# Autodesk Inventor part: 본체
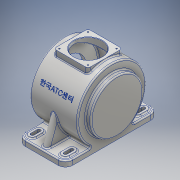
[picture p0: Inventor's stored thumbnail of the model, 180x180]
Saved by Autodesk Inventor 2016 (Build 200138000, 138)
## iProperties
Created: 2015-06
Part Number: 본체
Material: 알루미늄 6061
Document SubType Name: Modeling
Designer: Administrator
Density: 2.7 g/cm^3
Appearance: 알루미늄 - 평지
Mass: 3263.51 g
Surface Area: 2302.96 cm^2
Volume: 1208.71 cm^3
Author: Administrator
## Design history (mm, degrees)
sketch "스케치1"
  geometry: C1 r 85 at (0, 0); 1 further point
  constraints: 1 centre point, 1 coincident
  dimensions: "d0" = 170 diameter of C1
extrude "돌출1" new body sketch "스케치1" stored distance "d1" = 118; taper "d3" = 0 deg; dims "d2" = 51, "d4" = 0
sketch "스케치3"
  geometry: C1 r 65 at (0, 0); 1 further point
  constraints: 1 centre point, 1 coincident
  dimensions: "d5" = 130 diameter of C1
extrude "돌출2" join sketch "스케치3" distance "d6" = 13; taper "d7" = 0 deg
sketch "스케치4"
  geometry: C1 r 65 at (0, 0); 1 further point
  constraints: 1 centre point, 1 coincident
  dimensions: "d8" = 130 diameter of C1
extrude "돌출3" join sketch "스케치4" distance "d9" = 3; taper "d10" = 0 deg
sketch "스케치7"
  geometry: L1 (71, -115)-(85, -115); L2 (85, -115)-(85, 115); L3 (85, 115)-(71, 115); L4 (71, 115)-(71, -115); 2 further points
  constraints: 8 end point, 2 parallel, 1 horizontal, 1 horizontal alignment, 1 midpoint, 1 perpendicular
  dimensions: "d16" = 14 distance of L2.end L3.end; "d17" = 230 distance of L3.end L1.start; "d18" = 85 distance from line of L2 point (0, 0)
extrude "돌출5" join sketch "스케치7" stored distance "d19" = 3; taper "d20" = 0 deg
sketch "스케치8"
  geometry: L1 (-62, 65)-(-62, -65) reference; L2 (-59, -85)-(59, -85) reference; L3 (-59, 85)-(59, 85) reference; L4 (72, 0)-(-62, 0); L5 (-51, 47.5)-(-51, 77); L6 (-51, 77)-(51, 77); L7 (51, 77)-(51, 31); L8 (51, 31)-(47.5, 29.368); L9 (47.5, 29.368)-(47.5, 23.5); L10 (47.5, 23.5)-(61.5, 23.5); L11 (61.5, 23.5)-(61.5, 15); L12 (61.5, 15)-(64.5, 15); L13 (72, -65)-(72, 65) reference; L14 (64.5, 15)-(64.5, 0); L15 (-51, 47.5)-(-62, 47.5); L16 (-62, 47.5)-(-62, 0); 1 further point
  constraints: 24 end point, 5 perpendicular, 2 midpoint, 2 point on line, 1 parallel, 1 vertical
  dimensions: "d21" = 3 distance of L11.end L12.end; "d23" = 30 diameter of L12 L4; "d24" = 14 distance of L9.end L10.end; "d25" = 47 diameter of L10 L4; "d26" = 115 deg angle of L7 L8; "d27" = 102 distance between parallel lines of L5 L7; "d28" = 62 diameter of L7.end L4; "d29" = 154 diameter of L6 L4; "d30" = 95 diameter of L15 L4; "d31" = 11 distance of L5.start L15.end; "d32" = 3.5 distance from line of L7 L8.end
revolve "회전1" sketch "스케치8" stored, may be unused: angle "d33" = 90 deg
sketch "스케치9"
  geometry: L1 (-115, -71)-(-46.733, -71) reference; L2 (115, -85)-(-115, -85) reference; L3 (46.733, -71)-(115, -71) reference; L4 (-42.5, 88)-(42.5, 88); L5 (42.5, 88)-(42.5, 73.612); L6 (-42.5, 73.612)-(-42.5, 88); A1 r 85 centre (0, 0) between (46.733, -71) and (-46.733, -71) reference; 1 further point
  constraints: 6 end point, 2 parallel, 2 point on circle, 1 horizontal, 1 perpendicular
  dimensions: "d34" = 85 distance of L4.start L4.end; "d35" = 173 distance between parallel lines of L2 L4
extrude "돌출6" join sketch "스케치9" stored distance "d36" = 85; taper "d37" = 0 deg
sketch "스케치10"
  geometry: 2 further points
  constraints: 1 coincident
hole "구멍1" sketch "스케치10" at (42.5, 42.5) diameter "d38" = 70; stored, may be unused: countersink angle "d42" = 90 deg, drill point angle "d44" = 118 deg; dims "d39" = 6, "d40" = 4, "d41" = 2, "d43" = 8
fillet "모깎기1" dims "d45" = 7
sketch "스케치11"
  geometry: L1 (0, 78)-(71, 78); L2 (71, 78)-(71, 7); L3 (71, 7)-(0, 7); L4 (0, 7)-(0, 78); 7 further points
  constraints: 8 end point, 4 coincident, 2 midpoint, 2 parallel, 2 perpendicular, 1 horizontal, 1 horizontal alignment, 1 vertical alignment
  dimensions: "d46" = 71 distance of L1.start L1.end
hole "구멍2" sketch "스케치11" at (0, 78), (0, 7), (71, 7), (71, 78) diameter "d47" = 3.242; stored, may be unused: countersink angle "d51" = 90 deg, drill point angle "d53" = 118 deg; dims "d48" = 10, "d49" = 4, "d50" = 2, "d52" = 13
sketch "스케치12"
  geometry: A1 r 55 centre (0, 0) between (0, 55) and (55, 0); 3 further points
  constraints: 4 point on circle, 2 horizontal alignment, 2 vertical alignment, 1 centre point, 1 coincident
  dimensions: "d54" = 110 diameter of A1
hole "구멍3" sketch "스케치12" at (0, 55), (55, 0), (0, -55), (-55, 0) diameter "d55" = 3.242; stored, may be unused: countersink angle "d59" = 90 deg, drill point angle "d61" = 118 deg; dims "d56" = 8, "d57" = 4, "d58" = 2, "d60" = 11.8
sketch "스케치14"
  geometry: L1 (-115, -71)-(-46.733, -71) reference; L2 (-109, -71)-(-84.87, -4.703); L3 (-109, -71)-(-46.733, -71); A1 r 85 centre (0, 0) between (46.733, -71) and (-46.733, -71) reference; 1 further point
  constraints: 4 end point, 1 horizontal, 1 point on circle, 1 point on line
  dimensions: "d62" = 6 distance of L1.start L2.start; "d63" = 110 deg angle of L1 L2
extrude "돌출7" join sketch "스케치14" stored distance "d64" = 15; taper "d65" = 0 deg
sketch "스케치16"
  geometry: L1 (-18, 25.267)-(-18, 25.267); L2 (-9, 34.267)-(-9, 50.267); L3 (-18, 59.267)-(-18, 59.267); L4 (-27, 50.267)-(-27, 34.267); L5 (0, 68.267)-(-118, 68.267) reference; L6 (0, -161.733)-(0, 68.267) reference; L7 (0, -46.733)-(-118, -46.733); L8 (-118, 68.267)-(-118, -161.733) reference; L9 (-27, -127.733)-(-27, -143.733); L10 (-9, -143.733)-(-9, -127.733); L11 (-109, 50.267)-(-109, 34.267); L12 (-91, 34.267)-(-91, 50.267); L13 (-109, -127.733)-(-109, -143.733); L14 (-91, -143.733)-(-91, -127.733); A1 r 9 centre (-18, 50.267) between (-18, 59.267) and (-27, 50.267); A2 r 9 centre (-18, 50.267) between (-9, 50.267) and (-18, 59.267); A3 r 9 centre (-18, 34.267) between (-27, 34.267) and (-18, 25.267); A4 r 9 centre (-18, 34.267) between (-18, 25.267) and (-9, 34.267); A5 r 9 centre (-18, -143.733) between (-27, -143.733) and (-18, -152.733); A6 r 9 centre (-18, -143.733) between (-18, -152.733) and (-9, -143.733); A7 r 9 centre (-18, -127.733) between (-9, -127.733) and (-18, -118.733); A8 r 9 centre (-18, -127.733) between (-18, -118.733) and (-27, -127.733); A9 r 9 centre (-100, 34.267) between (-109, 34.267) and (-100, 25.267); A10 r 9 centre (-100, 34.267) between (-100, 25.267) and (-91, 34.267); A11 r 9 centre (-100, 50.267) between (-91, 50.267) and (-100, 59.267); A12 r 9 centre (-100, 50.267) between (-100, 59.267) and (-109, 50.267); A13 r 9 centre (-100, -143.733) between (-109, -143.733) and (-100, -152.733); A14 r 9 centre (-100, -143.733) between (-100, -152.733) and (-91, -143.733); A15 r 9 centre (-100, -127.733) between (-91, -127.733) and (-100, -118.733); A16 r 9 centre (-100, -127.733) between (-100, -118.733) and (-109, -127.733); 13 further points
  constraints: 32 point on circle, 22 end point, 16 centre point, 15 point on line, 8 tangent, 3 equal radius, 2 horizontal, 2 midpoint, 2 parallel, 1 perpendicular, 1 vertical, 63 other
  dimensions: "d67" = 18 distance of point (-9, 59.267) point (-27, 59.267); "d68" = 9 radius of A1; "d69" = 16 distance of A1.centre A3.centre; "d70" = 18 distance from line of A1.centre L6; "d71" = 194 diameter of A1.centre L7; "d74" = 178 distance of L4.start L9.start; "d77" = 82 distance of L4.start L11.start
extrude "돌출8" join sketch "스케치16" distance "d80" = 3; taper "d81" = 0 deg
sketch "스케치17"
  geometry: L1 (-22, 34.267)-(-22, 50.267); L2 (-14, 34.267)-(-14, 50.267); A1 r 9 centre (-18, 34.267) between (-27, 34.267) and (-9, 34.267) reference; A2 r 9 centre (-18, 50.267) between (-9, 50.267) and (-27, 50.267) reference; A3 r 4 centre (-18, 34.267) between (-22, 34.267) and (-14, 34.267); A4 r 4 centre (-18, 50.267) between (-14, 50.267) and (-22, 50.267); 1 further point
  constraints: 4 end point, 4 point on circle, 2 centre point, 2 coincident, 2 horizontal alignment, 2 tangent
  dimensions: "d88" = 8 diameter of A3; "d89" = 8 diameter of A4
extrude "돌출9" cut sketch "스케치17" stored distance "d90" = 3; taper "d91" = 0 deg
fillet "모깎기2" dims "d98" = 18
fillet "모깎기3" dims "d99" = 7.5
fillet "모깎기4" dims "d100" = 3
fillet "모깎기5" dims "d101" = 3
fillet "모깎기6" dims "d102" = 3
fillet "모깎기7" dims "d103" = 3
fillet "모깎기8" dims "d104" = 3
node "작업 평면1"
sketch "스케치19"
  geometry: 3 further points
  constraints: 1 coincident, 1 other
extrude "돌출10" join sketch "스케치19" distance "d106" = 0.5; taper "d107" = 0 deg
chamfer "모따기1" distance "d108" = 1; stored, may be unused: second distance "d109" = 2, angle "d110" = 45 deg
fillet "모깎기9" dims "d111" = 3, "d112" = 0.3
fillet "모깎기10" dims "d113" = 3
node "솔리드1"
mirror "대칭1"
pattern_linear "직사각형 패턴2" dims "d94" = 178, "d97" = 82
